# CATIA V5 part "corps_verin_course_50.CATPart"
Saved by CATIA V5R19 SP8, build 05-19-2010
Part number: corps_verin_course_50
Bounding box of the stored display mesh (mm): x -19 to 18.975, y -18.92 to 19, z -171.5 to 0
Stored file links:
  C:\Users\ThinkMotion\Desktop\EU_thinkMotion\iao\IAO_MMS_Groupe3\avercruysse\IAO_vercruysse\IAO_vercruysse\corps_verin_course_50.CATPart
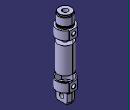
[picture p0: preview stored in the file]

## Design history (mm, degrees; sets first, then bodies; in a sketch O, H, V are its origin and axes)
Body1 "corps principal" (main body)
  Solid1 "1": solid without history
